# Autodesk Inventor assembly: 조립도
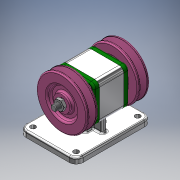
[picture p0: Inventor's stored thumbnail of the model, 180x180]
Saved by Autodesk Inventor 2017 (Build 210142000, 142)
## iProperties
Part Number: 조립도
Material: 일반
Document SubType Name: Assembly
Designer: 00-00
Author: 00-00
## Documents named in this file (10)
- C:\Users\00-00\Desktop\701106v1041\조립도.iam
- C:\Users\00-00\Desktop\701106v1041\본체.ipt
- C:\Users\00-00\Desktop\701106v1041\V-벨트풀리.ipt
- C:\Users\00-00\Desktop\701106v1041\너트 M10x1.ipt
- C:\Users\00-00\Desktop\701106v1041\베어링 6004.ipt
- C:\Users\00-00\Desktop\701106v1041\볼트 M4.ipt
- C:\Users\00-00\Desktop\701106v1041\오일 실 17 30 5.ipt
- C:\Users\00-00\Desktop\701106v1041\축.ipt
- C:\Users\00-00\Desktop\701106v1041\커버.ipt
- C:\Users\00-00\Desktop\701106v1041\키 5 x 5 x 12.ipt
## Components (2 placed, 1 different names)
1. V-벨트풀리:1
2. V-벨트풀리:2
## Component patterns: 구성요소 패턴 1:2 (2 elements), 구성요소 패턴 3:2 (2 elements)
